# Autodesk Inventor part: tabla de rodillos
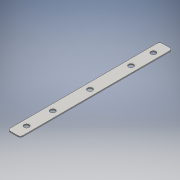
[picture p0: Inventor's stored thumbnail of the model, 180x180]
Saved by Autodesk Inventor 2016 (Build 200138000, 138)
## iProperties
Created: 2016-06
Part Number: tabla de rodillos
Material: Genérico
Document SubType Name: Modeling
Designer: adm
Density: 1 g/cm^3
Appearance: Valor por defecto
Author: adm
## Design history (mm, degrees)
sketch "Boceto1"
  geometry: L1 (-25, -300)-(25, -300); L2 (25, -300)-(25, 300); L3 (25, 300)-(-25, 300); L4 (-25, 300)-(-25, -300); L5 (-25, -300)-(25, 300); L6 (25, -300)-(-25, 300); C1 r 10 at (0, 250); C2 r 10 at (0, -250); 3 further points
  constraints: 12 end point, 2 centre point, 2 coincident, 2 midpoint, 2 parallel, 1 horizontal, 1 perpendicular
  dimensions: "d0" = 50 distance of L3.end L2.end; "d1" = 600 distance of L2.end L1.end; "d2" = 50 distance from line of point (0, 250) L3; "d3" = 20 diameter of C1; "d4" = 50 distance from line of L1 point (0, -250); "d5" = 20 diameter of C2
extrude "Extrusión1" new body sketch "Boceto1" distance "d6" = 4; taper "d7" = 0 deg
fillet "Empalme1" dims "d8" = 10
sketch "Boceto2"
  geometry: C1 r 10 at (0, 162.025); C2 r 10 at (0, 0); C3 r 10 at (0, -146.872); 4 further points
  constraints: 4 coincident, 3 centre point
  dimensions: "d9" = 20 diameter of C1; "d10" = 20 diameter of C2; "d11" = 20 diameter of C3
extrude "Extrusión2" cut sketch "Boceto2" distance "d12" = 10; taper "d13" = 0 deg
node "Sólido1"
